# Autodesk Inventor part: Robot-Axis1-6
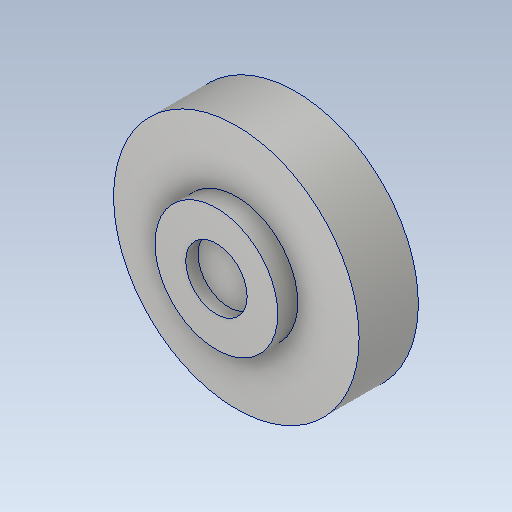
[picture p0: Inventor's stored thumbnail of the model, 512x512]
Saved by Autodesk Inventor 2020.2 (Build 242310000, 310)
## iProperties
Created: 2018-07
Part Number: Robot-Axis1-6
Material: Aluminum 6061
Description: 123456
Document SubType Name: Modeling
Designer: Power User
Mass: 280.594 g
Surface Area: 159.719 cm^2
Volume: 103.924 cm^3
Density: 2.7 g/cm^3
Appearance: Aluminum - Flat
Title: GEAR
Author: Power User
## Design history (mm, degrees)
sketch "Sketch6"
  geometry: C1 r 40 at (0, 0); C2 r 20 at (0, 0); 1 further point
  constraints: 2 centre point, 2 coincident
  dimensions: "d44" = 80 diameter of C1; "d45" = 40 diameter of C2
extrude "Extrusion5" new body sketch "Sketch6" distance "d46" = 19.3; taper "d47" = 0 deg
extrude "Extrusion6" join sketch "Sketch6" distance "d48" = 25.8; taper "d49" = 0 deg
sketch "Sketch7"
  geometry: C1 r 20 at (0, 0) reference; 2 further points
  constraints: 1 coincident
hole "Hole2" sketch "Sketch7" at (0, 0) diameter "d50" = 20; stored, may be unused: countersink angle "d54" = 90 deg, drill point angle "d56" = 0 deg; dims "d51" = 6, "d52" = 4, "d53" = 2, "d55" = 4
body "Solid2"
